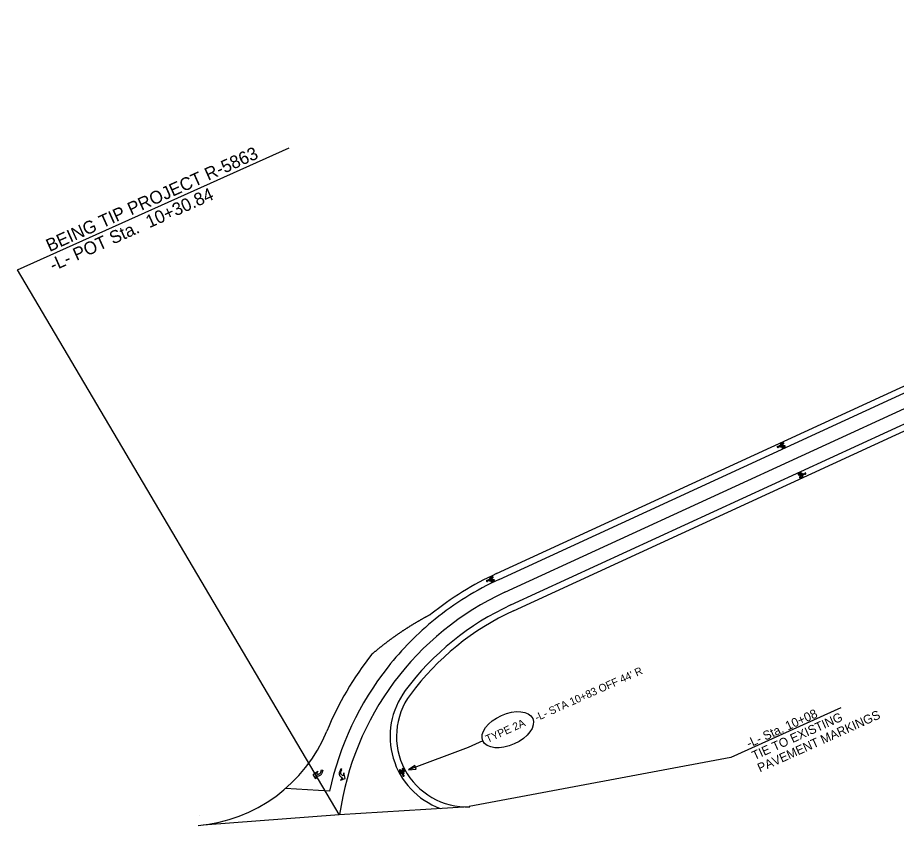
# Model space of a CAD drawing. Extents: x 553958 to 562499, y 493978 to 516388.
# Drawn here: x 558334 to 559022, y 493978 to 494610 of the extents above; entities that cross this region are included whole.
import ezdxf

# ---------------------------------------------------------------- set-up
doc = ezdxf.new("R2010")
doc.units = 0
for name, color, linetype in [('Prop Approach Slab', 7, 'Continuous'), ('Prop Dimension', 7, 'Continuous'), ('Prop DSN Text', 7, 'Continuous'), ('Prop EOT', 7, 'Continuous'), ('Prop Horizontal Alignment Curve and Spiral Data', 7, 'Continuous'), ('Prop Horizontal Alignment Direction Label', 7, 'Continuous'), ('Prop Horizontal Alignment Tick Small', 7, 'Continuous'), ('Prop SS Fill Line', 7, 'Continuous'), ('Sheet North Arrow CELL', 7, 'Continuous'), ('Sheet Plan CELL', 7, 'Continuous'), ('Sheet Plot Border Inside CELL', 7, 'Continuous'), ('Sheet Plot Border Outside CELL', 7, 'Continuous')]:
    doc.layers.add(name, color=color, linetype=linetype)

msp = doc.modelspace()

# ---------------------------------------------------------------- linework, layer by layer
at = {"layer": 'Prop Approach Slab'}
for p, q in [((558334.26, 494412.42), (558546.73, 494507.82)), ((558585.95, 493986.56), (558334.26, 494412.42))]:
    msp.add_line(p, q, dxfattribs=at)
msp.add_lwpolyline([(558978.18, 494069.85), (558892.18, 494031.24), (558687.45, 493992.74)], dxfattribs=at)
at = {"layer": 'Prop Dimension'}
msp.add_line((558476.3, 493985.67), (558476.3, 493985.67), dxfattribs=at)
at = {"layer": 'Prop DSN Text'}
msp.add_ellipse((558717.76, 494052.87), major_axis=(19.52, 8.77), ratio=0.570089, dxfattribs=at)
at = {"layer": 'Prop EOT'}
msp.add_arc((558810, 493955.07), 237, 129.01194, 141.688, dxfattribs=at)
at = {"layer": 'Prop Horizontal Alignment Curve and Spiral Data'}
for points in [[(558587.98, 494021.78), (558587.06, 494022.17), (558586.05, 494019.8), (558585.89, 494019.35), (558585.81, 494018.99), (558585.77, 494018.58), (558585.8, 494018.2), (558585.86, 494017.9), (558585.99, 494017.49), (558586.14, 494017.19), (558586.32, 494016.85), (558586.59, 494016.48), (558586.83, 494016.24), (558587.18, 494015.96), (558587.68, 494015.66), (558588.42, 494015.35), (558586.93, 494013.54), (558590.55, 494014.81), (558589.46, 494019.08), (558589.04, 494016.81), (558588.43, 494017.07), (558588.09, 494017.23), (558587.81, 494017.46), (558587.61, 494017.68), (558587.37, 494018), (558587.23, 494018.27), (558587.11, 494018.68), (558587.08, 494019.1), (558587.1, 494019.5), (558587.23, 494020.02)], [(558587.98, 494021.78), (558587.06, 494022.17), (558586.05, 494019.8), (558585.89, 494019.35), (558585.81, 494018.99), (558585.77, 494018.58), (558585.8, 494018.2), (558585.86, 494017.9), (558585.99, 494017.49), (558586.14, 494017.19), (558586.32, 494016.85), (558586.59, 494016.48), (558586.83, 494016.25), (558587.18, 494015.96), (558587.68, 494015.66), (558588.42, 494015.35), (558586.93, 494013.54), (558590.55, 494014.81), (558589.46, 494019.08), (558589.04, 494016.81), (558588.43, 494017.07), (558588.09, 494017.23), (558587.81, 494017.46), (558587.61, 494017.68), (558587.37, 494018), (558587.23, 494018.27), (558587.11, 494018.68), (558587.08, 494019.1), (558587.1, 494019.5), (558587.23, 494020.02)]]:
    msp.add_lwpolyline(points, close=True, dxfattribs=at)
at = {"layer": 'Prop Horizontal Alignment Direction Label'}
msp.add_lwpolyline([(558571.99, 494021.6), (558572.95, 494021.31), (558572.2, 494018.84), (558572.04, 494018.39), (558571.88, 494018.06), (558571.64, 494017.72), (558571.38, 494017.45), (558571.14, 494017.26), (558570.78, 494017.03), (558570.47, 494016.89), (558570.12, 494016.75), (558569.67, 494016.63), (558569.34, 494016.6), (558568.89, 494016.6), (558568.31, 494016.7), (558567.54, 494016.93), (558567.53, 494014.58), (558565.56, 494017.87), (558569.12, 494020.46), (558568, 494018.45), (558568.64, 494018.26), (558569, 494018.17), (558569.36, 494018.16), (558569.65, 494018.2), (558570.04, 494018.3), (558570.32, 494018.41), (558570.67, 494018.65), (558570.96, 494018.96), (558571.21, 494019.28), (558571.44, 494019.76)], close=True, dxfattribs=at)
msp.add_lwpolyline([(558571.99, 494021.6), (558572.95, 494021.31), (558572.2, 494018.84), (558572.04, 494018.39), (558571.88, 494018.06), (558571.64, 494017.72), (558571.38, 494017.45), (558571.14, 494017.26), (558570.78, 494017.03), (558570.47, 494016.89), (558570.12, 494016.75), (558569.67, 494016.63), (558569.34, 494016.6), (558568.89, 494016.6), (558568.31, 494016.7), (558567.54, 494016.93), (558567.53, 494014.58), (558565.56, 494017.87), (558569.12, 494020.46), (558568, 494018.45), (558568.64, 494018.26), (558569, 494018.17), (558569.36, 494018.16), (558569.65, 494018.2), (558570.04, 494018.3), (558570.32, 494018.41), (558570.67, 494018.65), (558570.96, 494018.96), (558571.21, 494019.28), (558571.44, 494019.76)], close=True, dxfattribs=at)
at = {"layer": 'Prop Horizontal Alignment Tick Small'}
for p, q in [((558929.46, 494274.49), (558930.95, 494275.25)), ((558930.95, 494275.25), (558933.06, 494275.4)), ((558932.11, 494276.96), (558932.2, 494276.74)), ((558932.11, 494276.96), (558932.2, 494276.74)), ((558932.53, 494275.99), (558932.63, 494275.77)), ((558932.53, 494275.99), (558932.63, 494275.77)), ((558933.06, 494275.4), (558933.1, 494275.17)), ((558928.92, 494274.41), (558928.86, 494274.55)), ((558928.92, 494274.41), (558928.86, 494274.55)), ((558929.31, 494273.51), (558929.25, 494273.65)), ((558929.31, 494273.51), (558929.25, 494273.65)), ((558929.67, 494274.24), (558929.46, 494274.49)), ((558930.95, 494273.83), (558929.67, 494274.24)), ((558930.9, 494274.88), (558929.93, 494274.38)), ((558929.93, 494274.38), (558931.23, 494273.95)), ((558931.63, 494274.18), (558930.9, 494274.88)), ((558931.23, 494273.95), (558930.95, 494273.83)), ((558933.08, 494275.17), (558931.09, 494275.02)), ((558931.09, 494275.02), (558931.65, 494274.49)), ((558932.32, 494274.67), (558931.63, 494274.18)), ((558931.65, 494274.49), (558932.18, 494274.86)), ((558932.18, 494274.86), (558932.32, 494274.67)), ((558933.08, 494274.72), (558933.18, 494274.5)), ((558933.08, 494274.72), (558933.18, 494274.5)), ((558933.51, 494273.75), (558933.6, 494273.52)), ((558933.51, 494273.75), (558933.6, 494273.52)), ((558946, 494253.26), (558945.9, 494253.48)), ((558946, 494253.26), (558945.9, 494253.48)), ((558946.44, 494252.29), (558946.34, 494252.52)), ((558946.44, 494252.29), (558946.34, 494252.52)), ((558946.49, 494251.61), (558946.44, 494251.84)), ((558946.46, 494251.85), (558948.45, 494252.04)), ((558948.59, 494251.81), (558946.49, 494251.61)), ((558947.03, 494251.04), (558946.93, 494251.26)), ((558947.03, 494251.04), (558946.93, 494251.26)), ((558947.21, 494252.36), (558947.88, 494252.87)), ((558947.35, 494252.17), (558947.21, 494252.36)), ((558947.87, 494252.56), (558947.35, 494252.17)), ((558947.48, 494250.08), (558947.37, 494250.3)), ((558947.48, 494250.08), (558947.37, 494250.3)), ((558948.45, 494252.04), (558947.87, 494252.56)), ((558947.88, 494252.87), (558948.63, 494252.19)), ((558948.28, 494253.11), (558948.56, 494253.24)), ((558949.59, 494252.71), (558948.28, 494253.11)), ((558948.56, 494253.24), (558949.84, 494252.85)), ((558950.06, 494252.61), (558948.59, 494251.81)), ((558948.63, 494252.19), (558949.59, 494252.71)), ((558949.84, 494252.85), (558950.06, 494252.61)), ((558950.19, 494253.59), (558950.25, 494253.45)), ((558950.19, 494253.59), (558950.25, 494253.45)), ((558950.6, 494252.71), (558950.66, 494252.57)), ((558950.6, 494252.71), (558950.66, 494252.57)), ((558704.65, 494172.2), (558704.74, 494171.98)), ((558704.65, 494172.2), (558704.74, 494171.98)), ((558701.46, 494169.65), (558701.4, 494169.79)), ((558701.46, 494169.65), (558701.4, 494169.79)), ((558701.85, 494168.75), (558701.79, 494168.89)), ((558701.85, 494168.75), (558701.79, 494168.89)), ((558702, 494169.73), (558703.49, 494170.49)), ((558702.21, 494169.48), (558702, 494169.73)), ((558703.49, 494169.07), (558702.21, 494169.48)), ((558703.44, 494170.12), (558702.47, 494169.62)), ((558702.47, 494169.62), (558703.77, 494169.19)), ((558704.17, 494169.42), (558703.44, 494170.12)), ((558703.49, 494170.49), (558705.6, 494170.64)), ((558703.77, 494169.19), (558703.49, 494169.07)), ((558705.62, 494170.41), (558703.63, 494170.26)), ((558703.63, 494170.26), (558704.19, 494169.73)), ((558704.86, 494169.91), (558704.17, 494169.42)), ((558704.19, 494169.73), (558704.72, 494170.1)), ((558704.72, 494170.1), (558704.86, 494169.91)), ((558705.07, 494171.23), (558705.17, 494171.01)), ((558705.07, 494171.23), (558705.17, 494171.01)), ((558705.6, 494170.64), (558705.64, 494170.41)), ((558705.62, 494169.96), (558705.72, 494169.74)), ((558705.62, 494169.96), (558705.72, 494169.74)), ((558706.05, 494168.99), (558706.14, 494168.77)), ((558706.05, 494168.99), (558706.14, 494168.77)), ((558634.71, 494020.97), (558634.94, 494021.01)), ((558634.89, 494018.86), (558634.71, 494020.97)), ((558634.95, 494020.99), (558635.11, 494019)), ((558635.39, 494021), (558635.62, 494021.1)), ((558635.39, 494021), (558635.62, 494021.1)), ((558636.36, 494021.43), (558636.58, 494021.53)), ((558636.36, 494021.43), (558636.58, 494021.53)), ((558633.16, 494020), (558633.39, 494020.1)), ((558633.16, 494020), (558633.39, 494020.1)), ((558634.13, 494020.43), (558634.35, 494020.53)), ((558634.13, 494020.43), (558634.35, 494020.53)), ((558635.66, 494017.38), (558634.89, 494018.86)), ((558635.11, 494019), (558635.64, 494019.57)), ((558635.26, 494020.09), (558635.45, 494020.23)), ((558635.64, 494019.57), (558635.26, 494020.09)), ((558635.95, 494019.55), (558635.26, 494018.81)), ((558635.26, 494018.81), (558635.76, 494017.84)), ((558635.45, 494020.23), (558635.95, 494019.55)), ((558635.75, 494016.84), (558635.61, 494016.78)), ((558635.75, 494016.84), (558635.61, 494016.78)), ((558635.91, 494017.59), (558635.66, 494017.38)), ((558635.76, 494017.84), (558636.18, 494019.16)), ((558636.31, 494018.87), (558635.91, 494017.59)), ((558636.18, 494019.16), (558636.31, 494018.87)), ((558636.64, 494017.24), (558636.5, 494017.17)), ((558636.64, 494017.24), (558636.5, 494017.17))]:
    msp.add_line(p, q, dxfattribs=at)
for centre, radius, start, end in [((558929.08, 494274.03), 0.563, 113.55114, 293.55114), ((558929.08, 494274.03), 0.563, 113.55114, 293.55114), ((558929.08, 494274.03), 0.41, 293.55114, 113.55114), ((558950.43, 494253.08), 0.41, 114.91872, 294.91872), ((558950.43, 494253.08), 0.563, 294.91872, 114.91872), ((558950.43, 494253.08), 0.563, 294.91872, 114.91872), ((558701.63, 494169.27), 0.563, 113.55114, 293.55114), ((558701.63, 494169.27), 0.563, 113.55114, 293.55114), ((558701.63, 494169.27), 0.41, 293.55114, 113.55114), ((558636.13, 494017.01), 0.563, 204.18158, 24.18158), ((558636.13, 494017.01), 0.563, 204.18158, 24.18158), ((558636.13, 494017.01), 0.41, 24.18158, 204.18158)]:
    msp.add_arc(centre, radius, start, end, dxfattribs=at)
for centre, major_axis, ratio, start_param, end_param in [((558932.37, 494276.36), (1.37, 0.6), 0.435841, 1.570796, 4.712389), ((558932.37, 494276.36), (1.15, 0.5), 0.325967, 1.570796, 4.712389), ((558932.37, 494276.36), (1.37, 0.6), 0.435841, 4.712389, 7.853982), ((558932.37, 494276.36), (1.15, 0.5), 0.325967, 4.712389, 7.853982), ((558933.34, 494274.12), (1.37, 0.6), 0.435841, 1.570796, 4.712389), ((558933.34, 494274.12), (1.15, 0.5), 0.325967, 1.570796, 4.712389), ((558933.34, 494274.12), (1.37, 0.6), 0.435841, 4.712389, 7.853982), ((558933.34, 494274.12), (1.15, 0.5), 0.325967, 4.712389, 7.853982), ((558946.17, 494252.89), (-1.36, -0.63), 0.435841, 4.712389, 7.853982), ((558946.17, 494252.89), (-1.13, -0.53), 0.325967, 4.712389, 7.853982), ((558947.2, 494250.67), (-1.36, -0.63), 0.435841, 4.712389, 7.853982), ((558946.17, 494252.89), (-1.36, -0.63), 0.435841, 1.570796, 4.712389), ((558947.2, 494250.67), (-1.13, -0.53), 0.325967, 4.712389, 7.853982), ((558946.17, 494252.89), (-1.13, -0.53), 0.325967, 1.570796, 4.712389), ((558947.2, 494250.67), (-1.36, -0.63), 0.435841, 1.570796, 4.712389), ((558947.2, 494250.67), (-1.13, -0.53), 0.325967, 1.570796, 4.712389), ((558704.91, 494171.6), (1.37, 0.6), 0.435841, 1.570796, 4.712389), ((558704.91, 494171.6), (1.37, 0.6), 0.435841, 4.712389, 7.853982), ((558704.91, 494171.6), (1.15, 0.5), 0.325967, 4.712389, 7.853982), ((558704.91, 494171.6), (1.15, 0.5), 0.325967, 1.570796, 4.712389), ((558705.88, 494169.36), (1.37, 0.6), 0.435841, 1.570796, 4.712389), ((558705.88, 494169.36), (1.15, 0.5), 0.325967, 1.570796, 4.712389), ((558705.88, 494169.36), (1.37, 0.6), 0.435841, 4.712389, 7.853982), ((558705.88, 494169.36), (1.15, 0.5), 0.325967, 4.712389, 7.853982), ((558633.76, 494020.26), (-0.61, 1.36), 0.435841, 4.712389, 7.853982), ((558633.76, 494020.26), (-0.51, 1.14), 0.325967, 4.712389, 7.853982), ((558635.99, 494021.26), (-0.61, 1.36), 0.435841, 4.712389, 7.853982), ((558635.99, 494021.26), (-0.51, 1.14), 0.325967, 4.712389, 7.853982), ((558635.99, 494021.26), (-0.61, 1.36), 0.435841, 1.570796, 4.712389), ((558635.99, 494021.26), (-0.51, 1.14), 0.325967, 1.570796, 4.712389), ((558633.76, 494020.26), (-0.61, 1.36), 0.435841, 1.570796, 4.712389), ((558633.76, 494020.26), (-0.51, 1.14), 0.325967, 1.570796, 4.712389)]:
    msp.add_ellipse(centre, major_axis=major_axis, ratio=ratio, start_param=start_param, end_param=end_param, dxfattribs=at)
at = {"layer": 'Prop SS Fill Line'}
for p, q in [((558708.86, 494174.92), (559653.95, 494609.7)), ((558722.23, 494145.85), (559147.1, 494341.31)), ((558479.57, 493978.38), (558479.57, 493978.38))]:
    msp.add_line(p, q, dxfattribs=at)
for centre, radius, start, end in [((558810, 493955.07), 242, 114.70456, 129.01194), ((558810, 493955.07), 210, 114.70456, 143.32746), ((558810, 493955.07), 253, 141.688, 157.53406), ((558685.68, 494047.64), 55, 143.32746, 272.47458), ((558465.31, 494097.61), 120, 274.84868, 337.53406)]:
    msp.add_arc(centre, radius, start, end, dxfattribs=at)
msp.add_spline([(558657.67, 494143.11), (558657.01, 494142.77), (558656.36, 494142.42), (558655.7, 494142.08), (558655.05, 494141.73), (558654.4, 494141.38), (558653.74, 494141.03), (558653.09, 494140.67), (558652.44, 494140.32), (558651.79, 494139.96), (558651.14, 494139.6), (558650.49, 494139.23), (558649.85, 494138.87), (558649.2, 494138.5), (558648.55, 494138.13), (558647.91, 494137.76), (558647.27, 494137.38), (558646.62, 494137), (558645.98, 494136.63), (558645.34, 494136.24), (558644.7, 494135.86), (558644.05, 494135.48), (558643.42, 494135.09), (558642.78, 494134.7), (558642.14, 494134.31), (558641.5, 494133.91), (558640.87, 494133.51), (558640.23, 494133.12), (558639.6, 494132.71), (558638.96, 494132.31), (558638.33, 494131.91), (558637.7, 494131.5), (558637.07, 494131.09), (558636.44, 494130.68), (558635.81, 494130.26), (558635.18, 494129.85), (558634.55, 494129.43), (558633.93, 494129.01), (558633.3, 494128.58), (558632.68, 494128.16), (558632.05, 494127.73), (558631.43, 494127.3), (558630.81, 494126.87), (558630.19, 494126.43), (558629.57, 494126), (558628.95, 494125.56), (558628.33, 494125.12), (558627.72, 494124.68), (558627.1, 494124.23), (558626.49, 494123.79), (558625.87, 494123.34), (558625.26, 494122.89), (558624.65, 494122.43), (558624.04, 494121.98), (558623.43, 494121.52), (558622.82, 494121.06), (558622.22, 494120.6), (558621.61, 494120.13), (558621.01, 494119.67), (558620.4, 494119.2), (558619.8, 494118.73), (558619.2, 494118.25), (558618.6, 494117.78), (558618, 494117.3), (558617.4, 494116.82), (558616.8, 494116.34), (558616.21, 494115.86), (558615.61, 494115.37), (558615.02, 494114.89), (558614.43, 494114.4), (558613.84, 494113.9), (558613.25, 494113.41), (558612.66, 494112.91), (558611.49, 494111.91)], degree=3, dxfattribs=at)
at = {"layer": 'Sheet North Arrow CELL'}
msp.add_lwpolyline([(558578.25, 494004.69), (558543.77, 494006.81)], dxfattribs=at)
at = {"layer": 'Sheet Plan CELL'}
msp.add_lwpolyline([(558698.24, 494044.1), (558686.74, 494038.94), (558640.15, 494021.41)], dxfattribs=at)
msp.add_lwpolyline([(558645.03, 494024.9), (558640.15, 494021.41), (558646.13, 494022)], close=True, dxfattribs=at)
at = {"layer": 'Sheet Plot Border Inside CELL'}
for p, q in [((558708.86, 494174.92), (559653.95, 494609.7)), ((558710.95, 494170.38), (559656.04, 494605.16)), ((558720.14, 494150.39), (559145.01, 494345.85)), ((558722.23, 494145.85), (559147.1, 494341.31)), ((558479.57, 493978.38), (558479.57, 493978.38))]:
    msp.add_line(p, q, dxfattribs=at)
msp.add_lwpolyline([(558479.57, 493978.38), (558585.95, 493986.56), (558687.45, 493992.74)], dxfattribs=at)
for centre, radius, start, end in [((558810, 493955.07), 242, 114.70456, 129.01194), ((558810, 493955.07), 237, 114.70456, 129.01194), ((558810, 493955.07), 215, 114.70456, 143.32746), ((558810, 493955.07), 210, 114.70456, 143.32746), ((558810, 493955.07), 253, 141.688, 157.53406), ((558810, 493955.07), 237, 141.688, 167.91532), ((558685.68, 494047.64), 60, 143.32746, 249.70728), ((558685.68, 494047.64), 55, 143.32746, 272.47458), ((558465.31, 494097.61), 120, 274.84868, 337.53406)]:
    msp.add_arc(centre, radius, start, end, dxfattribs=at)
msp.add_spline([(558657.67, 494143.11), (558657.01, 494142.77), (558656.36, 494142.42), (558655.7, 494142.08), (558655.05, 494141.73), (558654.4, 494141.38), (558653.74, 494141.03), (558653.09, 494140.67), (558652.44, 494140.32), (558651.79, 494139.96), (558651.14, 494139.6), (558650.49, 494139.23), (558649.85, 494138.87), (558649.2, 494138.5), (558648.55, 494138.13), (558647.91, 494137.76), (558647.27, 494137.38), (558646.62, 494137), (558645.98, 494136.63), (558645.34, 494136.24), (558644.7, 494135.86), (558644.05, 494135.48), (558643.42, 494135.09), (558642.78, 494134.7), (558642.14, 494134.31), (558641.5, 494133.91), (558640.87, 494133.51), (558640.23, 494133.12), (558639.6, 494132.71), (558638.96, 494132.31), (558638.33, 494131.91), (558637.7, 494131.5), (558637.07, 494131.09), (558636.44, 494130.68), (558635.81, 494130.26), (558635.18, 494129.85), (558634.55, 494129.43), (558633.93, 494129.01), (558633.3, 494128.58), (558632.68, 494128.16), (558632.05, 494127.73), (558631.43, 494127.3), (558630.81, 494126.87), (558630.19, 494126.43), (558629.57, 494126), (558628.95, 494125.56), (558628.33, 494125.12), (558627.72, 494124.68), (558627.1, 494124.23), (558626.49, 494123.79), (558625.87, 494123.34), (558625.26, 494122.89), (558624.65, 494122.43), (558624.04, 494121.98), (558623.43, 494121.52), (558622.82, 494121.06), (558622.22, 494120.6), (558621.61, 494120.13), (558621.01, 494119.67), (558620.4, 494119.2), (558619.8, 494118.73), (558619.2, 494118.25), (558618.6, 494117.78), (558618, 494117.3), (558617.4, 494116.82), (558616.8, 494116.34), (558616.21, 494115.86), (558615.61, 494115.37), (558615.02, 494114.89), (558614.43, 494114.4), (558613.84, 494113.9), (558613.25, 494113.41), (558612.66, 494112.91), (558611.49, 494111.91)], degree=3, dxfattribs=at)
at = {"layer": 'Sheet Plot Border Outside CELL'}
msp.add_line((558715.55, 494160.38), (559678.69, 494603.47), dxfattribs=at)
msp.add_arc((558810, 493955.07), 226, 114.70456, 172, dxfattribs=at)

# ---------------------------------------------------------------- texts
at = {"layer": 'Prop Approach Slab'}
for s, height, p in [(' BEING TIP PROJECT R-5863', 10, (558355.93, 494424.82)), ('-L- POT Sta.  10+30.84', 10, (558362.07, 494411.14)), ('-L- Sta. 10+08', 7, (558906.39, 494038.56)), ('TIE TO EXISTING', 7, (558910.69, 494028.98)), ('PAVEMENT MARKINGS', 7, (558914.99, 494019.4))]:
    msp.add_text(s, height=height, rotation=24.18158, dxfattribs=at).set_placement(p)
at = {"layer": 'Prop EOT'}
for s, p in [("-L- STA 10+83 OFF 44' R", (558740.48, 494059.38)), ('TYPE 2A', (558701.99, 494042.5))]:
    msp.add_text(s, height=6, rotation=24.18158, dxfattribs=at).set_placement(p)

doc.saveas('drawing.dxf')
